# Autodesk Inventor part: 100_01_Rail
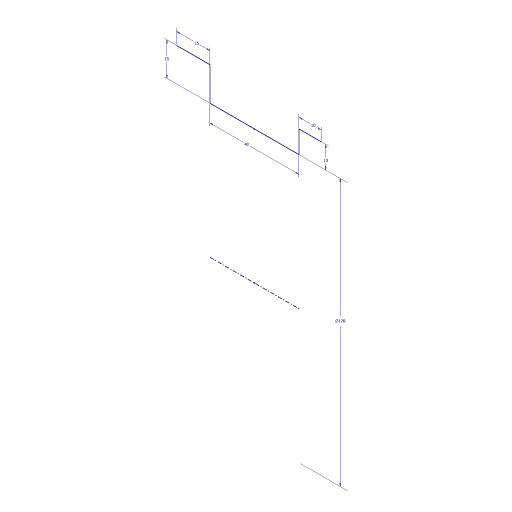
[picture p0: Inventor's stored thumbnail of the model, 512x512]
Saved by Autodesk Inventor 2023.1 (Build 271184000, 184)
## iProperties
Company: Fabian Stasiak CAD Consulting
Category: Autodesk® Inventor® Tutorial Series
Created: 2011-01
Part Number: 100_01_Rail
Material: Steel
Document SubType Name: Konstrukcja blachowa
Designer: F.Stasiak
Density: 7.85 g/cm^3
Sheet Metal Rule: Steel 2.5 mm/Round
Appearance: Semi-Polished
Catalog Web Link: www.expertbooks.eu
FLATAREA: =<FLAT PATTERN AREA>
Thickness: 2,500 mm
Author: F.Stasiak
Subject: Sheet Metal Design. Basic and Advanced techniques
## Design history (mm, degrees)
sketch "Sketch1"
  geometry: L1 (35, 15)-(20, 15); L2 (20, 15)-(20, 0); L3 (20, 0)-(-20, 0); L4 (-20, 0)-(-20, 10); L5 (-20, 10)-(-30, 10); L6 (20, -60)-(-20, -60); 3 further points
  constraints: 12 end point, 5 parallel, 2 midpoint, 1 coincident, 1 horizontal, 1 perpendicular, 1 vertical alignment
  dimensions: "d0" = 15 distance of L1.start L1.end; "d1" = 10 distance of L4.end L5.end; "d2" = 10 distance of L3.end L4.end; "d3" = 15 distance of L1.end L2.end; "d4" = 40 distance of L2.end L3.end; "d5" = 120 diameter of L3 L6
other parameters: "Thickness" = 2.5 (derived), "WspółczynnikK" = 4.4, "BendRadius" = 2.5 (= Thickness), "BendReliefWidth" = 2.5 (= Thickness), "BendReliefDepth" = 1.25 (= 0.5 x Thickness), "OdstępPołączenia" = 0.01, "MinimumRemnant" = 5 (= 2 x Thickness), "TransitionRadius" = 2.5 (= BendRadius), "JacobiRadiusSize" = 2.5 (= BendRadius), "GapSize" = 2.5 (= Thickness)
